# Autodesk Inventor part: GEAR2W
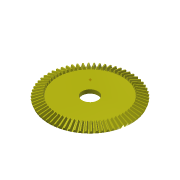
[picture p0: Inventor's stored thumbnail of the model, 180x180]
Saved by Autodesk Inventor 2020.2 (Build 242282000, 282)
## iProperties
Created: 2001-01
Part Number: GEAR2W
Material: Stal, miękka
Document SubType Name: Modeling
Description: Przekładnie zębate stożkowe 25/66, 4
Density: 7.86 g/cm^3
Appearance: Żółta
Designer: F.Stasiak
Manager: www.cadconsulting.pl
Company: Fabian Stasiak CAD Consulting
Control State: 0
Master: False
Checked Out: False
Shininess: 20.0
Length Units: 11269
Angle Units: 11279
Time Units: 11290
Mass Units: 11283
Length Display Precision: 3
Angle Display Precision: 2
+MSCProtocol1+ProtocolID: P00051221230142984
+MSCProtocol2+Protocol: P00051221230142984<@PID>[Globals]<@EL>Standard=DIN<@EL>FirstRun=0<@EL>Language=CZ<@EL>OldOwnerHwnd=                   <@EL>OwnerHwnd=983418<@EL>WDOperation=<@EL
Density: 7.86
Volumn: 5.864026952018771
Area: 31.42094824814569
PropertySet Name: Model Information
TAB_mte: 4
TAB_z1: 25
TAB_z2: 66
TAB_betam: 20
TAB_x: 0.1632
TAB_xt: 0
TAB_delta1: 20.7461
TAB_delta2: 69.2539
TAB_IT: 6e26
TAB_fpt1: ±0.011
TAB_fpt2: ±0.012
TAB_tfa: 0
TAB_sk1: 5.682
TAB_sk2: 4.883
TAB_ECs1: -0.04
TAB_ECd1: -0.1
TAB_ECs2: -0.056
TAB_ECd2: -0.136
TAB_hk1: 3.619
TAB_hk2: 2.459
TAB_omega: 90
TAB_de1: 100
TAB_de2: 264
TAB_le: 141.152
TAB_deltaf1: 19.0632
TAB_deltaf2: 67.0417
TAB_alfat: 20
Subject: Zbiór ćwiczeń. Autodesk Inventor 2020. Kurs podstawowy
Author: F.Stasiak
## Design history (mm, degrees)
node "Bryła1"
node "Korpusy bryłowe"
node "Korpusy powierzchniowe"
revolve "Base Body" stored, may be unused: angle "d10" = 360 deg
node "Tooth Plane"
workpoint "Work Point"
sketch "Sketch2"
  geometry: L1 (5.508, 5.108)-(-5.508, 5.108); L2 (0, -8.972)-(5.508, 5.108); L3 (-5.508, 5.108)-(0, -8.972); L4 (0, 2.5)-(0, -3) reference; L5 (0, 2.5)-(0, -3) reference; L6 (0, 2.5)-(0, -3) reference; L7 (0, -30.954)-(0, 16.239) reference; L8 (0, -30.954)-(0, 16.239) reference; L9 (19.305, -40.574)-(-25.74, -40.574) reference; A1 r 8.117 centre (0, -0.855) between (-5.508, 5.108) and (0, -8.972); 1 further point; 1 other entity
  constraints: 6 end point, 3 point on circle, 2 point on line, 1 centre point, 1 horizontal, 1 vertical alignment, 1 other
  dimensions: "d42" = 42.7273 deg angle of L3 L2 (= msp_a2); "d43" = 14.08 distance from line of L2.start L1 (= 1.6 x msp_he); "d54" = 34.85795 distance of L2.start point (0, -43.83) (= msp_y)
extrude "Tooth" cut sketch "Sketch2" distance "d18" = 30.6 (= 1.02 x prf_b); taper "d19" = -1.41691 deg (= msp_a1)
pattern_circular "Tooth Pattern" dims angle "d22" = 360 deg
revolve "Fix Body" stored, may be unused: angle "d23" = 360 deg
sketch "Sketch7"
  geometry: L1 (-12, 0)-(16, 0) reference; L2 (0, -12)-(0, 16) reference; 2 further points
  constraints: 1 coincident
hole "Hole" sketch "Sketch7" diameter "d47" = 65.03425 (= hole); stored, may be unused: countersink angle "d51" = 60 deg, drill point angle "d53" = 118 deg; dims "d48" = 6, "d49" = 4, "d50" = 2, "d52" = 8
node "Gear Axis"
node "Mesh Plane"
node "Intersection"
sketch "Szkic8"
  geometry: C1 r 25 at (0, 0); A1 r 102.424 centre (0, 0) between (-18.369, -100.764) and (-10.764, -101.857) reference
  constraints: 1 centre point, 1 coincident
  dimensions: "d69" = 50 diameter of C1
extrude "Wyciągnięcie proste2" cut sketch "Szkic8" extent not by distance; stored distance "d70" = 10; taper "d71" = 0 deg
sketch "Base Body Sketch"
  geometry: L1 (104.879, 6.48)-(102.424, 0); L2 (104.879, 6.48)-(133.185, -3.481); L3 (133.185, -3.481)-(130.069, -11.71); L4 (-1.609, 0)-(20.914, 0) reference; L5 (102.424, 0)-(0, 0); L6 (0, -11.71)-(130.069, -11.71); L7 (0, 0)-(0, -11.71); L8 (104.879, 6.48)-(0, 43.388); L9 (0, 0)-(0, 43.388); L10 (0, -22.98)-(0, 29.259) reference; L11 (0, 43.388)-(132, -6.612); L12 (0, 43.388)-(102.424, 0); L13 (102.424, 0)-(130.069, -11.71)
  constraints: 22 end point, 3 collinear, 2 parallel, 2 perpendicular, 2 point on line
  dimensions: "d33" = 30 distance between parallel lines of L3 L1 (= prf_b); "d34" = 266.371 diameter of L2.end L7 (= msp_dae); "d35" = 260.137 diameter of L3.end L7 (= msp_dfe); "d37" = 141.152 distance from line of L3 L8.end (= prf_le); "d41" = 69.2539 deg angle of L9 L11 (= msp_delta); "d59" = 102.42415 distance of L5.end L1.end (derived)
sketch "Sketch3"
  geometry: L1 (-102.424, 0)-(0, 0); L2 (-130.069, -11.71)-(-102.424, 0); L3 (0, -11.71)-(-130.069, -11.71); L4 (0, 0)-(0, -11.71); L5 (-130.069, -11.71)-(130.069, -11.71) reference; L6 (-102.424, 0)-(102.424, 0) reference; L7 (0, -21.174)-(0, 5.775) reference; 1 further point
  constraints: 8 end point, 2 horizontal, 2 point on line, 1 vertical
  dimensions: "d57" = 260.137 diameter of L2.start L7 (= msp_dfe); "d58" = 0 distance between parallel lines of L7 L4; "d60" = 102.42415 distance of L1.start L1.end (= d59)
other parameters: "prf_le" = 141.152 [user parameter; used in 3 equation terms], "prf_delta2" = 12.08709 [user parameter; used in 1 equation term], "prf_he2" = 8.8 [user parameter; used in 1 equation term], "prf_dfe2" = 260.137 [user parameter; used in 1 equation term], "prf_dae2" = 266.371 [user parameter; used in 1 equation term], "prf_de2" = 264 [user parameter; used in 1 equation term], "prf_b" = 30 [user parameter; used in 2 equation terms], "prf_omega" = 90 deg [user parameter; used in 1 equation term], "msp_delta" = 69.2539 deg (= prf_delta2) [user parameter; used in 3 equation terms], "msp_he" = 8.8 (= prf_he2) [user parameter; used in 2 equation terms], "msp_dfe" = 260.137 (= prf_dfe2) [user parameter; used in 3 equation terms], "msp_dae" = 266.371 (= prf_dae2) [user parameter; used in 2 equation terms], "msp_de" = 264 (= prf_de2) [user parameter; used in 1 equation term], "hole" = 65.03425 (= 0.25 x msp_dfe) [user parameter; used in 1 equation term], "msp_y" = 34.85795 (computed from msp_delta, msp_dae, msp_he) [user parameter; used in 1 equation term], "msp_a1" = -1.41691 deg (computed from msp_de, msp_z, prf_le) [user parameter; used in 1 equation term], "msp_a2" = 42.7273 deg (computed from msp_z) [user parameter; used in 1 equation term], "msp_dist" = 49.9999 (computed from prf_le, msp_delta) [user parameter], "d0" = 3.62545 (derived), "d4" = 38.7702 (derived), "d6" = 32.175 (derived), "d8" = 21.89 (derived), "d12" = 0 (derived), "d14" = -13.24579 (derived), "d16" = 9.83731 (derived), "d40" = 19.14 (derived), "d61" = 90 deg, "d64" = 0, "d65" = 90 deg (= prf_omega), "d66" = 3.78788 (computed from prf_z1, prf_z2), "d67" = 0, "d68" = 0
